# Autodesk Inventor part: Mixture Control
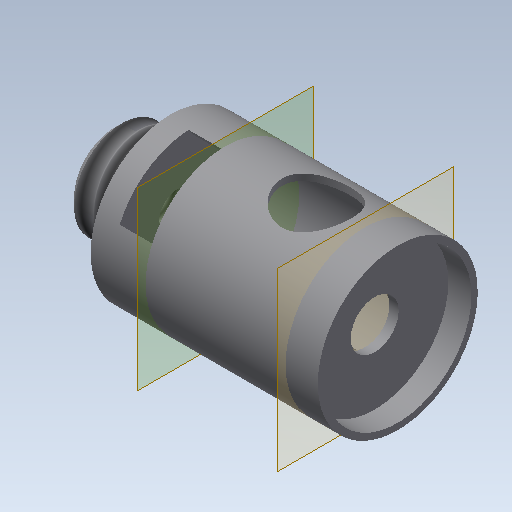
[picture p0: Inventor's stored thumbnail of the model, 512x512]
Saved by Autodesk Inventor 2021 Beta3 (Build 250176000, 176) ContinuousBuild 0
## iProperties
Created: 2012-08
Part Number: Mixture Control
Material: Generic
Document SubType Name: Modeling
Designer: John
Density: 1 g/cm^3
Appearance: Default
Author: John
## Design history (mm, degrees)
sketch "Sketch1"
  geometry: C1 r 5.296 at (0, 0); 1 further point
  constraints: 1 centre point, 1 coincident
  dimensions: "d0" = 10.5918 diameter of C1
extrude "Extrusion1" new body sketch "Sketch1" distance "d2" = 15.0368; taper "d3" = 0 deg
sketch "Sketch2"
  geometry: C1 r 5.296 at (0, 0) reference; C2 r 3.493 at (0, 0)
  constraints: 1 centre point, 1 coincident
  dimensions: "d4" = 6.985 diameter of C2
extrude "Extrusion2" join sketch "Sketch2" distance "d5" = 15.2908; taper "d6" = 0 deg
sketch "Sketch3"
  geometry: C1 r 5.296 at (0, 0) reference; C2 r 3.175 at (0, 0)
  constraints: 1 centre point, 1 coincident
  dimensions: "d8" = 6.35 diameter of C2
extrude "Extrusion3" join sketch "Sketch3" distance "d9" = 18.7706; taper "d10" = 0 deg
sketch "Sketch4"
  geometry: C1 r 5.296 at (0, 0) reference; C2 r 4.877 at (0, 0)
  constraints: 1 centre point, 1 coincident
  dimensions: "d11" = 9.7536 diameter of C2
extrude "Extrusion4" cut sketch "Sketch4" distance "d12" = 1.524; taper "d13" = 0 deg
workplane "Work Plane1"
sketch "Sketch5"
  geometry: C1 r 5.296 at (0, 0) reference; C2 r 4.877 at (0, 0); 1 further point
  constraints: 1 centre point, 1 coincident
  dimensions: "d15" = 9.7536 diameter of C2
extrude "Extrusion5" cut sketch "Sketch5" distance "d16" = 12.446; taper "d17" = 0 deg
sketch "Sketch6"
  geometry: C1 r 3.175 at (0, 0) reference
hole "Hole1" sketch "Sketch6" at (0, 0) diameter "d18" = 2.4892; stored, may be unused: countersink angle "d22" = 82 deg, drill point angle "d24" = 118 deg; dims "d19" = 19.05, "d20" = 9.525, "d21" = 6.35, "d23" = 25.4
sketch "Sketch7"
  geometry: C1 r 4.877 at (0, 0) reference
hole "Hole2" sketch "Sketch7" at (0, 0) diameter "d25" = 3.175; stored, may be unused: countersink angle "d29" = 82 deg, drill point angle "d31" = 118 deg; dims "d26" = 19.05, "d27" = 9.525, "d28" = 6.35, "d30" = 25.4
chamfer "Chamfer1" distance "d32" = 0.508; stored, may be unused: second distance "d33" = 3.175, angle "d34" = 45 deg
thread "Thread1" dims "d35" = 25.4, "d36" = 0
sketch "Sketch8"
  geometry: L1 (22.525, 0)-(-3.754, 0) reference; L2 (0, -4.877)-(0, 4.877) reference; C1 r 2.286 at (5.385, 0); 1 further point
  constraints: 1 centre point, 1 point on line
  dimensions: "d37" = 4.572 diameter of C1; "d39" = 5.3848 distance from line of L2 C1.centre
extrude "Extrusion6" cut sketch "Sketch8" extent not by distance; stored distance "d40" = 4.572 (= d37); taper "d41" = 0 deg
workplane "Work Plane2"
sketch "Sketch9"
  geometry: 1 further point
sketch "Sketch10"
  geometry: L1 (0.285, 5.288)-(4.849, 2.13); L2 (0.285, 5.288)-(0.732, 5.934); L3 (0.732, 5.934)-(5.296, 2.776); L4 (4.849, 2.13)-(5.296, 2.776); L5 (0.285, 5.288)-(0, 4.877); L6 (0, 4.877)-(4.564, 1.718); L7 (4.849, 2.13)-(4.564, 1.718); A1 r 5.296 centre (0, 0) between (0.285, 5.288) and (4.849, 2.13) reference; 2 further points
  constraints: 14 end point, 5 perpendicular, 3 point on circle, 1 collinear, 1 point on line, 1 tangent, 2 other
extrude "Extrusion7" cut sketch "Sketch10" distance "d43" = 2.159; taper "d44" = 0 deg
body "Solid1"
node "Project Cut Edges1"
node "Project Cut Edges2"
other parameters: "d14" = -2.1336, "d42" = -3.6322
